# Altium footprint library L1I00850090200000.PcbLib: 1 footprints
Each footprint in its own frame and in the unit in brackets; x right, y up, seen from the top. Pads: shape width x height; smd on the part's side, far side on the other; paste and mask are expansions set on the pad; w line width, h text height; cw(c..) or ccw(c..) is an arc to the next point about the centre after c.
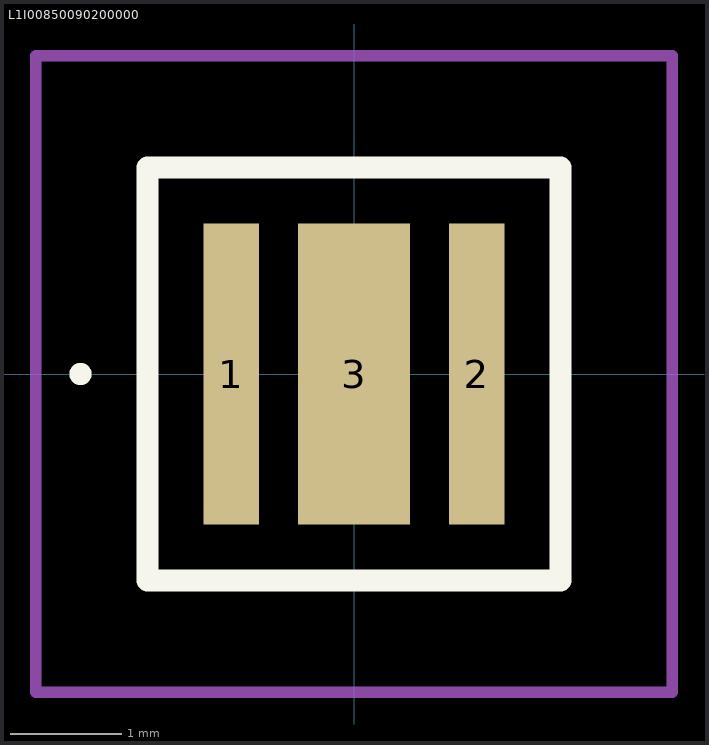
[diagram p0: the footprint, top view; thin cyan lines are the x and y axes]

## L1I00850090200000 [mm]
pads (3):
  rect 0.5x2.7 smd: 1(-1.1,0) 2(1.1,0)
  rect 1x2.7 smd: 3(0,0)
Top Overlay:
  lines w0.1: -2.5,0 cw(c-2.45,0) -2.4,0 ; -2.5,0 -2.5,0 ; -2.5,0 ccw(c-2.45,0) -2.4,0 ; -2.4,0 -2.4,0
  lines w0.2: -1.85,-1.85 1.85,-1.85 1.85,1.85 -1.85,1.85 -1.85,-1.85
Mechanical 15:
  lines w0.1: -1.85,-1.85 1.85,-1.85 1.85,1.85 -1.85,1.85 -1.85,-1.85
Mechanical 20:
  lines w0.1: -2.85,-2.85 2.85,-2.85 2.85,2.85 -2.85,2.85 -2.85,-2.85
